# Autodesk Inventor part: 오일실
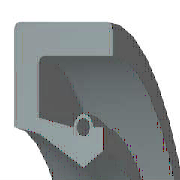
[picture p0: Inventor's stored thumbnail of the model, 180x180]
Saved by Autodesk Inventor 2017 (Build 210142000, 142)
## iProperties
IsCustomPart: 1
Created: 2015-12
Part Number: 오일실
Material: 고무
Description: 오일-실
Document SubType Name: Modeling
Standard: KS B 2804
Designer: mdu
Standards Organization: KS
Language: ko-KR
Size Designation: S - 15 30 7
Categories: <MemberInstance><Categories><Category DisplayName="샤프트 부품" InternalName="7f7aeb1f-a693-4053-b835-cee3144e0d98" Mnemonic="SHFT"><Category DisplayName="실링" Intern
Density: 0.93 g/cm^3
Appearance: 고무 - 검은색 - 버전 1.1
Author: mdu
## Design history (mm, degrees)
revolve "본체" stored, may be unused: angle "d17" = 90 deg
revolve "스프링1" stored, may be unused: angle "d18" = 90 deg
body "Solid1"
sketch "스케치1"
  geometry: L1 (0, 15)-(7, 15); L2 (7, 15)-(7, 13.75); L3 (7, 13.75)-(1.75, 13.75); L4 (0, 15)-(0, 9.6); L5 (0, 9.6)-(1.75, 9.25); L6 (1.75, 9.25)-(4.9, 7.5); L7 (4.9, 7.5)-(0, 7.5); L8 (6.3, 8.375)-(6.3, 9.6); L9 (0, 0)-(9.586, 0) reference; L10 (4.9, 7.5)-(6.3, 8.375); L11 (0, 18)-(0, -3) reference; L12 (-1.917, 0)-(11.503, 0) reference; L13 (4.2, 9.6)-(1.75, 10.09); L14 (1.75, 10.09)-(1.75, 13.75); L15 (6.3, 9.6)-(5.6, 9.6); C1 r 0.455 at (4.9, 9.6); A1 r 0.7 centre (4.9, 9.6) between (5.6, 9.6) and (4.2, 9.6)
  constraints: 26 end point, 5 horizontal alignment, 4 perpendicular, 2 centre point, 2 collinear, 2 horizontal, 2 parallel, 2 point on circle, 2 point on line, 2 vertical alignment, 1 coincident
  dimensions: "d0" = 30 diameter of L1 L9 (= SD2); "d1" = 16.75 diameter of L8.start L9 (= ABDM); "d2" = 1.25 distance of L1.end L2.end (computed from SD); "d3" = 0.91 diameter of C1 (= SPDI); "d4" = 1.4 diameter of A1 (= SPDA); "d5" = 15 diameter of L6.end L9 (= NND); "d6" = 18.5 diameter of L5.end L9 (= TKDM); "d7" = 19.2 diameter of L4.end L9 (= HLDM); "d8" = 4.9 distance from line of C1.centre L4 (= SPDST); "d9" = 6.3 distance between parallel lines of L8 L4 (= SDI); "d10" = 7 distance between parallel lines of L2 L4 (= SWDT); "d12" = 1.75 distance between parallel lines of L14 L4 (= SD)
fillet "모깎기1" dims "d11" = 0.3 (= RR)
other parameters: "SD2" = 30 [user parameter; used in 1 equation term], "SWDT" = 7 [user parameter; used in 1 equation term], "RR" = 0.3 [user parameter; used in 1 equation term], "SD" = 1.75 [user parameter; used in 2 equation terms], "NND" = 15 [user parameter; used in 1 equation term], "SPDA" = 1.4 [user parameter; used in 1 equation term], "SPDI" = 0.91 [user parameter; used in 1 equation term], "TKDM" = 18.5 [user parameter; used in 1 equation term], "HLDM" = 19.2 [user parameter; used in 1 equation term], "ABDM" = 16.75 [user parameter; used in 1 equation term], "SDI" = 6.3 [user parameter; used in 1 equation term], "SPDST" = 4.9 [user parameter; used in 1 equation term], "d13" = 0, "d14" = 0, "d15" = 0, "LAB" = 0.35 [user parameter]
